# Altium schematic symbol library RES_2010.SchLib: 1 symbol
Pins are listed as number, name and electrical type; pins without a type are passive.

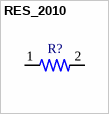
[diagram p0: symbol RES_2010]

## RES_2010
designator R?
1% 2W; MP: 1-2176071-4
footprint RES_2010
pins: 1, 2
